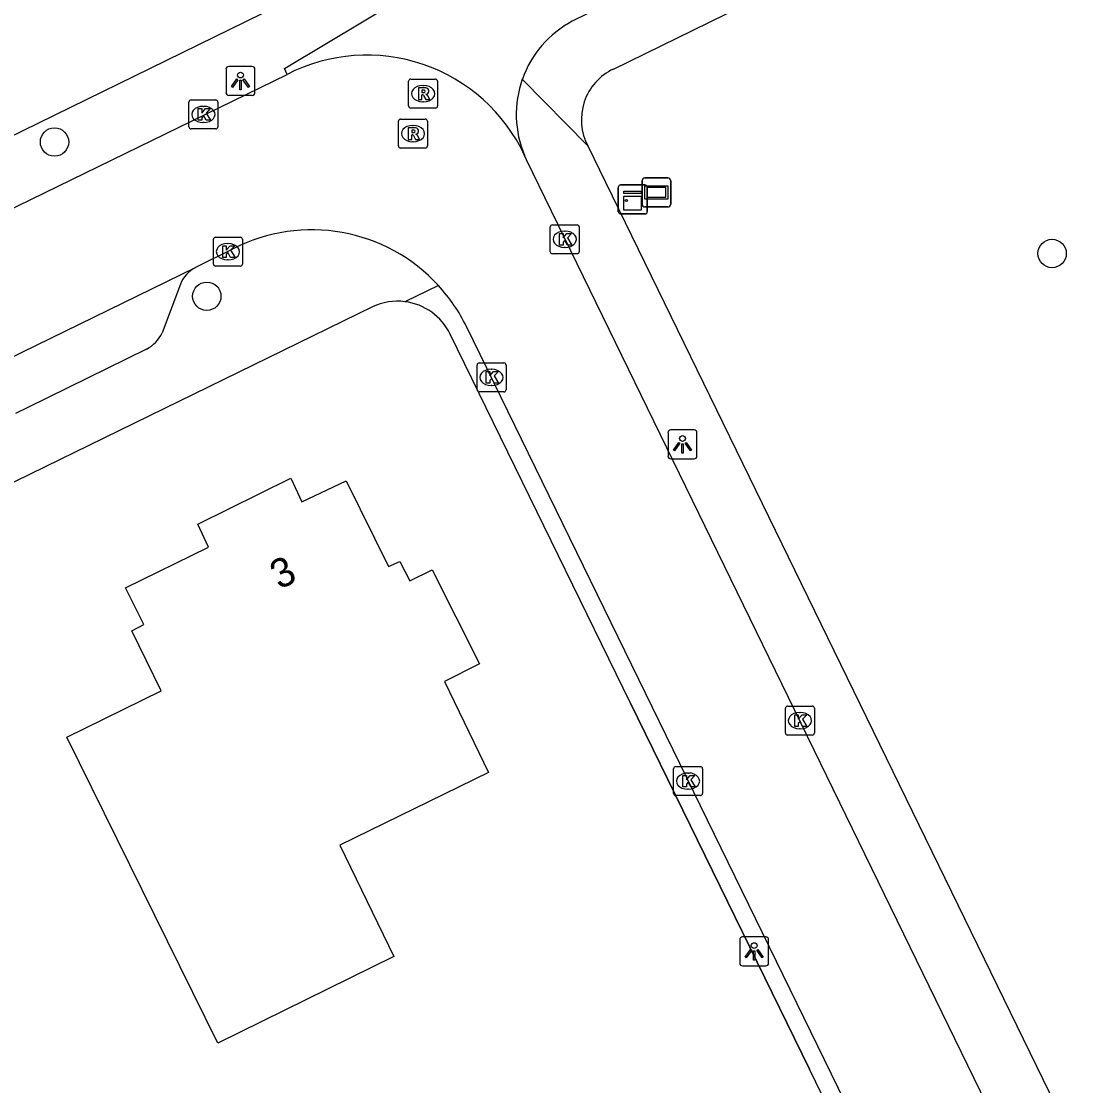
# Model space of a CAD drawing. Extents: x 160457 to 162082, y 388340 to 389736.
# Drawn here: x 160816.23 to 160852.84, y 388644.06 to 388680.79 of the extents above; entities that cross this region are included whole.
import ezdxf

# ---------------------------------------------------------------- set-up
doc = ezdxf.new("R2010")
doc.units = 0
for name, color, linetype in [('IMGEO_Boom', 7, 'Continuous'), ('IMGEO_Fietspad_gesloten', 7, 'Continuous'), ('IMGEO_Haag', 7, 'Continuous'), ('IMGEO_Kast', 7, 'Continuous'), ('IMGEO_Kolk', 7, 'Continuous'), ('IMGEO_Lichtpunt', 7, 'Continuous'), ('IMGEO_Muur', 7, 'Continuous'), ('IMGEO_Pand', 7, 'Continuous'), ('IMGEO_Pand_nummerreeks', 7, 'Continuous'), ('IMGEO_Rijbaan_lokaal_open', 7, 'Continuous'), ('IMGEO_Rioolput', 7, 'Continuous'), ('IMGEO_Straatnaambord', 7, 'Continuous'), ('IMGEO_Voetpad_open', 7, 'Continuous')]:
    doc.layers.add(name, color=color, linetype=linetype)

msp = doc.modelspace()

# ---------------------------------------------------------------- linework, layer by layer
at = {"layer": 'IMGEO_Boom'}
for centre in [(160817.375, 388676.619), (160851.79, 388672.774), (160822.629, 388671.299)]:
    msp.add_circle(centre, 0.489, dxfattribs=at)
at = {"layer": 'IMGEO_Fietspad_gesloten'}
for points in [[(160825.396, 388678.948), (160825.311, 388679.157), (160830.802, 388682.457), (160968.696, 388750), (161000, 388765.333), (161001.6, 388766.116)], [(160877.263, 388701.324), (160835.236, 388680.785)]]:
    msp.add_lwpolyline(points, dxfattribs=at)
for centre, radius, start, end in [((160836.936, 388677.576), 3.631, 117.9095, 160.4872), ((160836.935, 388677.573), 3.632, 160.4384, 202.9962)]:
    msp.add_arc(centre, radius, start, end, dxfattribs=at)
at = {"layer": 'IMGEO_Haag'}
msp.add_lwpolyline([(161000.979, 388767.447), (160965.347, 388750), (160778.313, 388658.421), (160776.807, 388656.846)], dxfattribs=at)
at = {"layer": 'IMGEO_Kast'}
for p, q in [((160836.823, 388674.215), (160836.823, 388675.056)), ((160836.823, 388675.056), (160836.823, 388674.215)), ((160836.898, 388675.14), (160837.739, 388675.14)), ((160837.739, 388675.14), (160836.898, 388675.14)), ((160837.823, 388675.065), (160837.823, 388674.224)), ((160837.823, 388674.224), (160837.823, 388675.065)), ((160837.748, 388674.14), (160836.907, 388674.14)), ((160836.907, 388674.14), (160837.748, 388674.14))]:
    msp.add_line(p, q, dxfattribs=at)
for points in [[(160837.018, 388674.93), (160837.618, 388674.93), (160837.618, 388674.845), (160837.018, 388674.845), (160837.018, 388674.93)], [(160837.018, 388674.755), (160837.618, 388674.755), (160837.618, 388674.266), (160837.018, 388674.266), (160837.018, 388674.755)]]:
    msp.add_lwpolyline(points, dxfattribs=at)
msp.add_circle((160837.102, 388674.604), 0.0377, dxfattribs=at)
for centre, start, end in [((160836.901, 388675.062), 92.4484, 184.2845), ((160836.901, 388675.062), 92.4484, 184.2845), ((160837.745, 388675.062), 2.4484, 94.2845), ((160837.745, 388675.062), 2.4484, 94.2845), ((160836.901, 388674.218), 182.4484, 274.2845), ((160836.901, 388674.218), 182.4484, 274.2845), ((160837.745, 388674.218), 272.4484, 4.2845), ((160837.745, 388674.218), 272.4484, 4.2845)]:
    msp.add_arc(centre, 0.0779, start, end, dxfattribs=at)
at = {"layer": 'IMGEO_Kolk'}
for p, q in [((160822.011, 388677.145), (160822.011, 388677.997)), ((160822.086, 388678.071), (160822.938, 388678.071)), ((160823.012, 388677.997), (160823.012, 388677.145)), ((160822.499, 388677.851), (160822.524, 388677.851)), ((160822.522, 388677.291), (160822.497, 388677.291)), ((160822.938, 388677.071), (160822.086, 388677.071)), ((160834.476, 388672.837), (160834.476, 388673.689)), ((160834.551, 388673.763), (160835.403, 388673.763)), ((160835.477, 388673.689), (160835.477, 388672.837)), ((160822.857, 388672.411), (160822.857, 388673.263)), ((160822.932, 388673.337), (160823.784, 388673.337)), ((160823.858, 388673.263), (160823.858, 388672.411)), ((160834.964, 388673.543), (160834.989, 388673.543)), ((160823.345, 388673.117), (160823.37, 388673.117)), ((160834.987, 388672.983), (160834.962, 388672.983)), ((160823.368, 388672.557), (160823.343, 388672.557)), ((160835.403, 388672.763), (160834.551, 388672.763)), ((160823.784, 388672.337), (160822.932, 388672.337)), ((160831.95, 388668.073), (160831.95, 388668.925)), ((160832.025, 388668.999), (160832.877, 388668.999)), ((160832.951, 388668.925), (160832.951, 388668.073)), ((160832.438, 388668.779), (160832.463, 388668.779)), ((160832.461, 388668.219), (160832.436, 388668.219)), ((160832.877, 388667.999), (160832.025, 388667.999)), ((160842.588, 388656.232), (160842.588, 388657.084)), ((160842.663, 388657.158), (160843.515, 388657.158)), ((160843.589, 388657.084), (160843.589, 388656.232)), ((160843.076, 388656.938), (160843.101, 388656.938)), ((160843.099, 388656.378), (160843.074, 388656.378)), ((160843.515, 388656.158), (160842.663, 388656.158)), ((160838.729, 388654.145), (160838.729, 388654.997)), ((160838.804, 388655.071), (160839.656, 388655.071)), ((160839.217, 388654.851), (160839.242, 388654.851)), ((160839.73, 388654.997), (160839.73, 388654.145)), ((160839.24, 388654.291), (160839.215, 388654.291)), ((160839.656, 388654.071), (160838.804, 388654.071))]:
    msp.add_line(p, q, dxfattribs=at)
for points in [[(160822.011, 388677.145), (160822.011, 388677.997)], [(160822.086, 388678.071), (160822.938, 388678.071)], [(160823.012, 388677.997), (160823.012, 388677.145)], [(160822.332, 388677.771), (160822.455, 388677.771), (160822.455, 388677.62), (160822.585, 388677.771), (160822.749, 388677.771), (160822.603, 388677.62), (160822.756, 388677.371), (160822.604, 388677.371), (160822.519, 388677.535), (160822.455, 388677.468), (160822.455, 388677.371), (160822.332, 388677.371), (160822.332, 388677.771)], [(160822.938, 388677.071), (160822.086, 388677.071)], [(160834.476, 388672.837), (160834.476, 388673.689)], [(160834.551, 388673.763), (160835.403, 388673.763)], [(160835.477, 388673.689), (160835.477, 388672.837)], [(160822.857, 388672.411), (160822.857, 388673.263)], [(160822.932, 388673.337), (160823.784, 388673.337)], [(160823.858, 388673.263), (160823.858, 388672.411)], [(160834.797, 388673.463), (160834.92, 388673.463), (160834.92, 388673.312), (160835.05, 388673.463), (160835.214, 388673.463), (160835.068, 388673.312), (160835.221, 388673.063), (160835.069, 388673.063), (160834.984, 388673.227), (160834.92, 388673.16), (160834.92, 388673.063), (160834.797, 388673.063), (160834.797, 388673.463)], [(160823.178, 388673.037), (160823.301, 388673.037), (160823.301, 388672.886), (160823.431, 388673.037), (160823.595, 388673.037), (160823.449, 388672.886), (160823.602, 388672.637), (160823.45, 388672.637), (160823.365, 388672.801), (160823.301, 388672.734), (160823.301, 388672.637), (160823.178, 388672.637), (160823.178, 388673.037)], [(160835.403, 388672.763), (160834.551, 388672.763)], [(160823.784, 388672.337), (160822.932, 388672.337)], [(160831.95, 388668.073), (160831.95, 388668.925)], [(160832.025, 388668.999), (160832.877, 388668.999)], [(160832.951, 388668.925), (160832.951, 388668.073)], [(160832.271, 388668.699), (160832.394, 388668.699), (160832.394, 388668.548), (160832.524, 388668.699), (160832.688, 388668.699), (160832.542, 388668.548), (160832.695, 388668.299), (160832.543, 388668.299), (160832.458, 388668.463), (160832.394, 388668.396), (160832.394, 388668.299), (160832.271, 388668.299), (160832.271, 388668.699)], [(160832.877, 388667.999), (160832.025, 388667.999)], [(160842.588, 388656.232), (160842.588, 388657.084)], [(160842.663, 388657.158), (160843.515, 388657.158)], [(160843.589, 388657.084), (160843.589, 388656.232)], [(160842.909, 388656.858), (160843.032, 388656.858), (160843.032, 388656.707), (160843.162, 388656.858), (160843.326, 388656.858), (160843.18, 388656.707), (160843.333, 388656.458), (160843.181, 388656.458), (160843.096, 388656.622), (160843.032, 388656.555), (160843.032, 388656.458), (160842.909, 388656.458), (160842.909, 388656.858)], [(160843.515, 388656.158), (160842.663, 388656.158)], [(160838.729, 388654.145), (160838.729, 388654.997)], [(160838.804, 388655.071), (160839.656, 388655.071)], [(160839.73, 388654.997), (160839.73, 388654.145)], [(160839.05, 388654.771), (160839.173, 388654.771), (160839.173, 388654.62), (160839.303, 388654.771), (160839.467, 388654.771), (160839.321, 388654.62), (160839.474, 388654.371), (160839.322, 388654.371), (160839.237, 388654.535), (160839.173, 388654.468), (160839.173, 388654.371), (160839.05, 388654.371), (160839.05, 388654.771)], [(160839.656, 388654.071), (160838.804, 388654.071)]]:
    msp.add_lwpolyline(points, dxfattribs=at)
for centre, start, end in [((160822.088, 388677.995), 91.552, 178.448), ((160822.088, 388677.995), 91.552, 178.448), ((160822.936, 388677.995), 1.552, 88.448), ((160822.936, 388677.995), 1.552, 88.448), ((160822.088, 388677.147), 181.552, 268.448), ((160822.088, 388677.147), 181.552, 268.448), ((160822.936, 388677.147), 271.552, 358.448), ((160822.936, 388677.147), 271.552, 358.448), ((160834.553, 388673.687), 91.552, 178.448), ((160834.553, 388673.687), 91.552, 178.448), ((160835.401, 388673.687), 1.552, 88.448), ((160835.401, 388673.687), 1.552, 88.448), ((160822.934, 388673.261), 91.552, 178.448), ((160822.934, 388673.261), 91.552, 178.448), ((160823.782, 388673.261), 1.552, 88.448), ((160823.782, 388673.261), 1.552, 88.448), ((160834.553, 388672.839), 181.552, 268.448), ((160834.553, 388672.839), 181.552, 268.448), ((160835.401, 388672.839), 271.552, 358.448), ((160835.401, 388672.839), 271.552, 358.448), ((160822.934, 388672.413), 181.552, 268.448), ((160822.934, 388672.413), 181.552, 268.448), ((160823.782, 388672.413), 271.552, 358.448), ((160823.782, 388672.413), 271.552, 358.448), ((160832.027, 388668.923), 91.552, 178.448), ((160832.027, 388668.923), 91.552, 178.448), ((160832.875, 388668.923), 1.552, 88.448), ((160832.875, 388668.923), 1.552, 88.448), ((160832.027, 388668.075), 181.552, 268.448), ((160832.027, 388668.075), 181.552, 268.448), ((160832.875, 388668.075), 271.552, 358.448), ((160832.875, 388668.075), 271.552, 358.448), ((160842.665, 388657.082), 91.552, 178.448), ((160842.665, 388657.082), 91.552, 178.448), ((160843.513, 388657.082), 1.552, 88.448), ((160843.513, 388657.082), 1.552, 88.448), ((160842.665, 388656.234), 181.552, 268.448), ((160842.665, 388656.234), 181.552, 268.448), ((160843.513, 388656.234), 271.552, 358.448), ((160843.513, 388656.234), 271.552, 358.448), ((160838.806, 388654.995), 91.552, 178.448), ((160838.806, 388654.995), 91.552, 178.448), ((160839.654, 388654.995), 1.552, 88.448), ((160839.654, 388654.995), 1.552, 88.448), ((160838.806, 388654.147), 181.552, 268.448), ((160838.806, 388654.147), 181.552, 268.448), ((160839.654, 388654.147), 271.552, 358.448), ((160839.654, 388654.147), 271.552, 358.448)]:
    msp.add_arc(centre, 0.0765, start, end, dxfattribs=at)
for centre, major_axis, ratio, start_param, end_param in [((160822.498, 388677.571), (-0.387, 0.002), 0.722429, 4.712389, 7.853982), ((160822.523, 388677.571), (-0.39, 0.002), 0.717154, 1.570796, 4.712389), ((160834.963, 388673.263), (-0.387, 0.002), 0.722429, 4.712389, 7.853982), ((160834.988, 388673.263), (-0.39, 0.002), 0.717154, 1.570796, 4.712389), ((160823.344, 388672.837), (-0.387, 0.002), 0.722429, 4.712389, 7.853982), ((160823.369, 388672.837), (-0.39, 0.002), 0.717154, 1.570796, 4.712389), ((160832.437, 388668.499), (-0.387, 0.002), 0.722429, 4.712389, 7.853982), ((160832.462, 388668.499), (-0.39, 0.002), 0.717154, 1.570796, 4.712389), ((160843.075, 388656.658), (-0.387, 0.002), 0.722429, 4.712389, 7.853982), ((160843.1, 388656.658), (-0.39, 0.002), 0.717154, 1.570796, 4.712389), ((160839.216, 388654.571), (-0.387, 0.002), 0.722429, 4.712389, 7.853982), ((160839.241, 388654.571), (-0.39, 0.002), 0.717154, 1.570796, 4.712389)]:
    msp.add_ellipse(centre, major_axis=major_axis, ratio=ratio, start_param=start_param, end_param=end_param, dxfattribs=at)
at = {"layer": 'IMGEO_Lichtpunt'}
for p, q in [((160823.291, 388679.132), (160823.291, 388678.325)), ((160823.291, 388679.132), (160823.291, 388678.325)), ((160824.193, 388679.227), (160823.385, 388679.227)), ((160824.193, 388679.227), (160823.385, 388679.227)), ((160824.287, 388678.325), (160824.287, 388679.132)), ((160824.287, 388678.325), (160824.287, 388679.132)), ((160823.385, 388678.231), (160824.193, 388678.231)), ((160823.385, 388678.231), (160824.193, 388678.231)), ((160838.539, 388666.592), (160838.539, 388665.785)), ((160838.539, 388666.592), (160838.539, 388665.785)), ((160839.441, 388666.687), (160838.633, 388666.687)), ((160839.441, 388666.687), (160838.633, 388666.687)), ((160839.535, 388665.785), (160839.535, 388666.592)), ((160839.535, 388665.785), (160839.535, 388666.592)), ((160838.633, 388665.691), (160839.441, 388665.691)), ((160838.633, 388665.691), (160839.441, 388665.691)), ((160841.013, 388649.1), (160841.013, 388648.293)), ((160841.013, 388649.1), (160841.013, 388648.293)), ((160841.915, 388649.195), (160841.107, 388649.195)), ((160841.915, 388649.195), (160841.107, 388649.195)), ((160842.009, 388648.293), (160842.009, 388649.1)), ((160842.009, 388648.293), (160842.009, 388649.1)), ((160841.107, 388648.199), (160841.915, 388648.199)), ((160841.107, 388648.199), (160841.915, 388648.199))]:
    msp.add_line(p, q, dxfattribs=at)
for points in [[(160823.665, 388678.796), (160823.704, 388678.768), (160823.516, 388678.506), (160823.478, 388678.533), (160823.665, 388678.796)], [(160823.767, 388678.748), (160823.814, 388678.748), (160823.814, 388678.426), (160823.767, 388678.426), (160823.767, 388678.748)], [(160823.877, 388678.768), (160823.915, 388678.795), (160824.102, 388678.533), (160824.063, 388678.505), (160823.877, 388678.768)], [(160838.913, 388666.256), (160838.952, 388666.228), (160838.764, 388665.966), (160838.726, 388665.993), (160838.913, 388666.256)], [(160839.125, 388666.228), (160839.163, 388666.255), (160839.35, 388665.993), (160839.311, 388665.965), (160839.125, 388666.228)], [(160839.015, 388666.208), (160839.062, 388666.208), (160839.062, 388665.886), (160839.015, 388665.886), (160839.015, 388666.208)], [(160841.387, 388648.764), (160841.426, 388648.736), (160841.238, 388648.474), (160841.2, 388648.501), (160841.387, 388648.764)], [(160841.489, 388648.716), (160841.536, 388648.716), (160841.536, 388648.394), (160841.489, 388648.394), (160841.489, 388648.716)], [(160841.599, 388648.736), (160841.637, 388648.763), (160841.824, 388648.501), (160841.785, 388648.473), (160841.599, 388648.736)]]:
    msp.add_lwpolyline(points, dxfattribs=at)
for centre in [(160823.79, 388678.93), (160839.038, 388666.39), (160841.512, 388648.898)]:
    msp.add_circle(centre, 0.0994, dxfattribs=at)
for centre, start, end in [((160823.385, 388679.132), 90, 180), ((160823.385, 388679.132), 90, 180), ((160824.193, 388679.132), 0, 90), ((160824.193, 388679.132), 0, 90), ((160823.385, 388678.325), 180, 270), ((160823.385, 388678.325), 180, 270), ((160824.193, 388678.325), 270, 0), ((160824.193, 388678.325), 270, 360), ((160838.633, 388666.592), 90, 180), ((160838.633, 388666.592), 90, 180), ((160839.441, 388666.592), 0, 90), ((160839.441, 388666.592), 0, 90), ((160838.633, 388665.785), 180, 270), ((160838.633, 388665.785), 180, 270), ((160839.441, 388665.785), 270, 0), ((160839.441, 388665.785), 270, 360), ((160841.107, 388649.1), 90, 180), ((160841.107, 388649.1), 90, 180), ((160841.915, 388649.1), 0, 90), ((160841.915, 388649.1), 0, 90), ((160841.107, 388648.293), 180, 270), ((160841.107, 388648.293), 180, 270), ((160841.915, 388648.293), 270, 0), ((160841.915, 388648.293), 270, 360)]:
    msp.add_arc(centre, 0.0946, start, end, dxfattribs=at)
at = {"layer": 'IMGEO_Muur'}
msp.add_lwpolyline([(160837.247, 388657.263), (160843.424, 388644.633)], dxfattribs=at)
at = {"layer": 'IMGEO_Pand'}
msp.add_lwpolyline([(160823.01, 388645.527), (160817.8, 388656.093), (160821.058, 388657.687), (160820.046, 388659.761), (160820.453, 388659.972), (160819.819, 388661.238), (160822.688, 388662.645), (160822.32, 388663.434), (160825.532, 388665.022), (160825.908, 388664.207), (160827.439, 388664.93), (160828.902, 388661.979), (160829.288, 388662.149), (160829.63, 388661.483), (160830.408, 388661.861), (160832.031, 388658.622), (160830.829, 388658.006), (160832.351, 388654.868), (160827.219, 388652.358), (160829.079, 388648.52), (160823.01, 388645.527)], dxfattribs=at)
at = {"layer": 'IMGEO_Rijbaan_lokaal_open'}
for points in [[(160777.453, 388655.571), (160825.396, 388678.948)], [(160850.209, 388642.046), (160834.521, 388674.235), (160833.659, 388676.005), (160833.592, 388676.154)], [(160823.539, 388672.939), (160822.242, 388672.292)], [(160815.237, 388668.87), (160822.242, 388672.292)], [(160844.897, 388642.996), (160831.585, 388670.25)]]:
    msp.add_lwpolyline(points, dxfattribs=at)
for centre, radius, start, end in [((160828.151, 388673.612), 6.006, 25.0446, 117.3071), ((160826.245, 388667.652), 5.939, 42.519, 117.1034), ((160826.262, 388667.665), 5.918, 25.9001, 42.5379)]:
    msp.add_arc(centre, radius, start, end, dxfattribs=at)
at = {"layer": 'IMGEO_Rioolput'}
for p, q in [((160829.59, 388677.863), (160829.59, 388678.715)), ((160829.665, 388678.789), (160830.517, 388678.789)), ((160830.591, 388678.715), (160830.591, 388677.863)), ((160830.078, 388678.569), (160830.103, 388678.569)), ((160830.101, 388678.009), (160830.076, 388678.009)), ((160830.517, 388677.789), (160829.665, 388677.789)), ((160829.24, 388676.484), (160829.24, 388677.336)), ((160829.315, 388677.41), (160830.167, 388677.41)), ((160830.241, 388677.336), (160830.241, 388676.484)), ((160829.728, 388677.19), (160829.753, 388677.19)), ((160829.751, 388676.63), (160829.726, 388676.63)), ((160830.167, 388676.41), (160829.315, 388676.41))]:
    msp.add_line(p, q, dxfattribs=at)
for points in [[(160829.59, 388677.863), (160829.59, 388678.715)], [(160829.665, 388678.789), (160830.517, 388678.789)], [(160830.591, 388678.715), (160830.591, 388677.863)], [(160830.179, 388678.487), (160829.927, 388678.489), (160829.927, 388678.089)], [(160830.105, 388678.408), (160830.051, 388678.408), (160830.051, 388678.327)], [(160829.927, 388678.089), (160830.051, 388678.089), (160830.051, 388678.251), (160830.062, 388678.251)], [(160830.051, 388678.327), (160830.103, 388678.327)], [(160830.109, 388678.222), (160830.18, 388678.089), (160830.32, 388678.089), (160830.255, 388678.215)], [(160830.517, 388677.789), (160829.665, 388677.789)], [(160829.24, 388676.484), (160829.24, 388677.336)], [(160829.315, 388677.41), (160830.167, 388677.41)], [(160830.241, 388677.336), (160830.241, 388676.484)], [(160829.829, 388677.108), (160829.577, 388677.11), (160829.577, 388676.71)], [(160829.577, 388676.71), (160829.701, 388676.71), (160829.701, 388676.872), (160829.712, 388676.872)], [(160829.755, 388677.029), (160829.701, 388677.029), (160829.701, 388676.948)], [(160829.701, 388676.948), (160829.753, 388676.948)], [(160829.759, 388676.843), (160829.83, 388676.71), (160829.97, 388676.71), (160829.905, 388676.836)], [(160830.167, 388676.41), (160829.315, 388676.41)]]:
    msp.add_lwpolyline(points, dxfattribs=at)
for centre, radius, start, end in [((160829.667, 388678.713), 0.0765, 91.552, 178.448), ((160829.667, 388678.713), 0.0765, 91.552, 178.448), ((160830.515, 388678.713), 0.0765, 1.552, 88.448), ((160830.515, 388678.713), 0.0765, 1.552, 88.448), ((160830.087, 388678.516), 0.19, 274.7715, 282.9687), ((160830.111, 388678.312), 0.0964, 77.0061, 93.1865), ((160830.125, 388678.369), 0.0378, 276.6634, 79.6772), ((160830.178, 388678.377), 0.109, 350.3612, 89.416), ((160830.176, 388678.377), 0.112, 277.5842, 350.9817), ((160830.061, 388678.198), 0.0533, 26.0293, 88.6989), ((160830.16, 388678.162), 0.108, 29.5134, 73.7905), ((160829.667, 388677.865), 0.0765, 181.552, 268.448), ((160829.667, 388677.865), 0.0765, 181.552, 268.448), ((160830.515, 388677.865), 0.0765, 271.552, 358.448), ((160830.515, 388677.865), 0.0765, 271.552, 358.448), ((160829.317, 388677.334), 0.0765, 91.552, 178.448), ((160829.317, 388677.334), 0.0765, 91.552, 178.448), ((160830.165, 388677.334), 0.0765, 1.552, 88.448), ((160830.165, 388677.334), 0.0765, 1.552, 88.448), ((160829.711, 388676.819), 0.0533, 26.0293, 88.6989), ((160829.737, 388677.137), 0.19, 274.7715, 282.9687), ((160829.761, 388676.933), 0.0964, 77.0061, 93.1865), ((160829.775, 388676.99), 0.0378, 276.6634, 79.6772), ((160829.828, 388676.998), 0.109, 350.3612, 89.416), ((160829.826, 388676.998), 0.112, 277.5842, 350.9817), ((160829.81, 388676.783), 0.108, 29.5134, 73.7905), ((160829.317, 388676.486), 0.0765, 181.552, 268.448), ((160829.317, 388676.486), 0.0765, 181.552, 268.448), ((160830.165, 388676.486), 0.0765, 271.552, 358.448), ((160830.165, 388676.486), 0.0765, 271.552, 358.448)]:
    msp.add_arc(centre, radius, start, end, dxfattribs=at)
for centre, major_axis, ratio, start_param, end_param in [((160830.077, 388678.289), (-0.387, 0.002), 0.722429, 4.712389, 7.853982), ((160830.102, 388678.289), (-0.39, 0.002), 0.717154, 1.570796, 4.712389), ((160829.727, 388676.91), (-0.387, 0.002), 0.722429, 4.712389, 7.853982), ((160829.752, 388676.91), (-0.39, 0.002), 0.717154, 1.570796, 4.712389)]:
    msp.add_ellipse(centre, major_axis=major_axis, ratio=ratio, start_param=start_param, end_param=end_param, dxfattribs=at)
at = {"layer": 'IMGEO_Straatnaambord'}
for p, q in [((160837.644, 388674.479), (160837.644, 388675.279)), ((160837.644, 388675.279), (160837.644, 388674.479)), ((160837.744, 388675.379), (160838.534, 388675.379)), ((160838.534, 388675.379), (160837.744, 388675.379)), ((160838.634, 388675.279), (160838.634, 388674.479)), ((160838.634, 388674.479), (160838.634, 388675.279)), ((160838.534, 388674.379), (160837.744, 388674.379)), ((160837.744, 388674.379), (160838.534, 388674.379))]:
    msp.add_line(p, q, dxfattribs=at)
for points in [[(160837.745, 388675.111), (160838.533, 388675.111), (160838.533, 388674.647), (160837.745, 388674.647), (160837.745, 388675.111)], [(160837.81, 388675.046), (160837.81, 388674.712), (160838.468, 388674.712), (160838.468, 388675.046), (160837.81, 388675.046)]]:
    msp.add_lwpolyline(points, dxfattribs=at)
for centre, start, end in [((160837.744, 388675.279), 90, 180), ((160837.744, 388675.279), 90, 180), ((160838.534, 388675.279), 0, 90), ((160838.534, 388675.279), 360, 90), ((160837.744, 388674.479), 180, 270), ((160837.744, 388674.479), 180, 270), ((160838.534, 388674.479), 270, 0), ((160838.534, 388674.479), 270, 0)]:
    msp.add_arc(centre, 0.1, start, end, dxfattribs=at)
at = {"layer": 'IMGEO_Voetpad_open'}
for points in [[(160836.66, 388679.137), (160877.596, 388699.187)], [(160833.513, 388678.789), (160835.778, 388676.486)], [(160835.778, 388676.486), (160836.388, 388675.234), (160851.912, 388643.364)], [(160821.716, 388671.714), (160821.087, 388670.037)], [(160830.622, 388671.666), (160829.463, 388671.111)], [(160828.347, 388670.932), (160777.455, 388646.059)], [(160846.054, 388639.234), (160843.424, 388644.633), (160837.247, 388657.263), (160831.025, 388669.988)], [(160820.547, 388669.479), (160816.449, 388667.461), (160816.026, 388667.255)]]:
    msp.add_lwpolyline(points, dxfattribs=at)
for centre, radius, start, end in [((160837.475, 388677.394), 1.925, 115.0626, 208.1323), ((160822.751, 388671.301), 1.114, 117.1668, 158.2267), ((160829.213, 388669.104), 2.023, 82.8874, 115.3372), ((160829.21, 388669.112), 2.015, 25.7784, 82.7931), ((160820.044, 388670.506), 1.144, 296.1005, 335.7779)]:
    msp.add_arc(centre, radius, start, end, dxfattribs=at)

# ---------------------------------------------------------------- texts
at = {"layer": 'IMGEO_Pand_nummerreeks'}
msp.add_text('3', height=1, rotation=26.3076, dxfattribs=at).set_placement((160825.132, 388661.165))

doc.saveas('drawing.dxf')
